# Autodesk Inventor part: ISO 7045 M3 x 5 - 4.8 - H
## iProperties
Created: 2004-09
Part Number: ISO 7045 M3 x 5 - 4.8 - H
Material: Standard
Catalog Web Link: file:///C:/Programme/Autodesk/Inventor 5.3/Content/Din/index.htm?doNavigateId=7A3AD77C-C431-11D4-A9F1-0080AD303E0A|31199D93B16811D4BA6900C04F798F98|true
Description: Flachkopfschraube mit Kreuzschlitz
Document SubType Name: Standard Catalog Part
Standard: ISO 7045 M3 x 5 - 4.8 - H
Designer: Ulrich
Control State: 0
Master: False
Checked Out: False
Shininess: 20.0
Angle Display Precision: 2
Document Length Units: 11269
Document Angle Units: 11279
Document Time Units: 11290
Document Mass Units: 11283
Document Length Units Precision: 3
Document Angle Units Precision: 2
Compacted: True
KLASSIFIKATION: 31161501 un/spsc
HERSTELLER: DIN Normsystem
Density: 0.0
Volumn: 0.0
Area: 0.0
PropertySet Name: Model Information
Author: Ulrich
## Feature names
1. Basis1
